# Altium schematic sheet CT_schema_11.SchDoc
size 147 x 119 mm
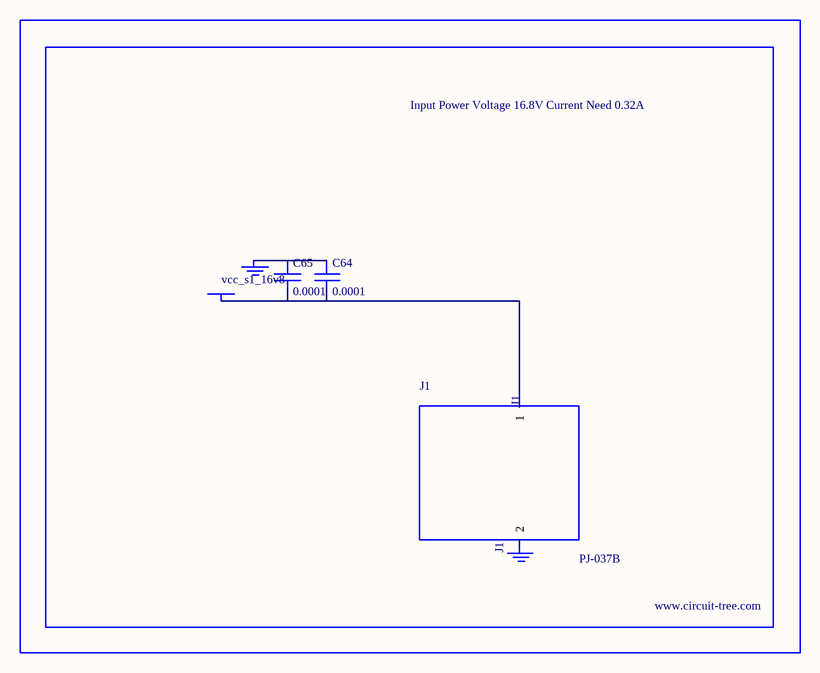
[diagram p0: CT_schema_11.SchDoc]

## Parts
BORDER10  (no value)
C64  0.0001  [EXV-9H]
C65  0.0001  [EXV-9H]
GND_INSTANCE_10_0  (no value)
GND_INSTANCE_10_1  (no value)
J1  PJ-037B  [PJ-037B_PACKAGE]
POWER_INSTANCE_10_0  vcc_s1_16v8

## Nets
NetC64_1: C64.1 C65.1 GND_INSTANCE_10_0.0(GND)
NetC64_2: C64.2 C65.2 J1.1 POWER_INSTANCE_10_0.0(PWR)

Not connected (* = marked no-connect by the designer): GND_INSTANCE_10_1 0(GND); J1 2

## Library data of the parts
BORDER10 = BORDER_PAGE10
C64 C65 = EDK107M035A9HAA
GND_INSTANCE_10_0 GND_INSTANCE_10_1 = GND
POWER_INSTANCE_10_0 = PWR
